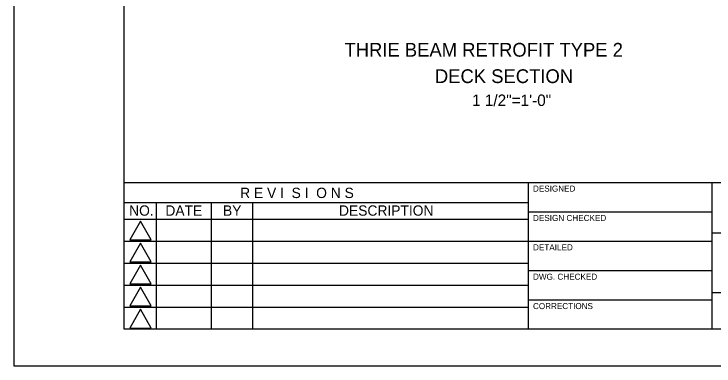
# Model space of a CAD drawing. Extents: x 0 to 22.7, y 0 to 15.7.
# Drawn here: x 0 to 6.35, y 0 to 3.2 of the extents above; entities that cross this region are included whole.
import ezdxf

# ---------------------------------------------------------------- set-up
doc = ezdxf.new("R2010")
doc.units = 0
for name, color, linetype in [('BORDER_ANNO_Cutsheet', 7, 'Continuous'), ('BRDG_ANNO_Anno-Sheet', 7, 'Continuous'), ('BRDG_ANNO_General-Notes', 7, 'Continuous'), ('BRDG_BASE_Active-Point', 7, 'Continuous')]:
    doc.layers.add(name, color=color, linetype=linetype)

msp = doc.modelspace()

# ---------------------------------------------------------------- linework, layer by layer
at = {"layer": 'BORDER_ANNO_Cutsheet'}
msp.add_lwpolyline([(0, 14.6667), (22.6667, 14.6667), (22.6667, 0), (0, 0)], close=True, dxfattribs=at)
at = {"layer": 'BRDG_ANNO_Anno-Sheet'}
for p, q in [((1, 1.6667), (12.8333, 1.6667)), ((4.6667, 0.3333), (4.6667, 1.6667)), ((6.3333, 0.3333), (6.3333, 1.6667)), ((1, 1.4833), (4.6667, 1.4833)), ((1.2917, 0.3333), (1.2917, 1.4833)), ((1.7917, 0.3333), (1.7917, 1.4833)), ((2.1667, 0.3333), (2.1667, 1.4796)), ((4.6667, 1.4), (6.3333, 1.4)), ((0.9983, 1.3333), (4.6667, 1.3333)), ((6.3333, 1.2083), (7.6667, 1.2083)), ((0.9983, 1.1333), (4.6667, 1.1333)), ((4.6667, 1.1333), (6.3333, 1.1333)), ((0.9983, 0.9333), (4.6667, 0.9333)), ((4.6667, 0.8667), (6.3333, 0.8667)), ((0.9983, 0.7333), (4.6667, 0.7333)), ((6.3333, 0.6667), (7.6667, 0.6667)), ((4.6667, 0.6), (6.3333, 0.6)), ((0.9983, 0.5333), (4.6667, 0.5333))]:
    msp.add_line(p, q, dxfattribs=at)
msp.add_lwpolyline([(1, 14.3333), (22.3333, 14.3333), (22.3333, 0.3333), (1, 0.3333)], close=True, dxfattribs=at)
for points in [[(1.1483, 1.3162), (1.0496, 1.145), (1.2429, 1.145), (1.1483, 1.3162)], [(1.1483, 1.1162), (1.0496, 0.945), (1.2429, 0.945), (1.1483, 1.1162)], [(1.1483, 0.9163), (1.0496, 0.745), (1.2429, 0.745), (1.1483, 0.9163)], [(1.1483, 0.7162), (1.0496, 0.545), (1.2429, 0.545), (1.1483, 0.7162)], [(1.1483, 0.5162), (1.0496, 0.345), (1.2429, 0.345), (1.1483, 0.5162)]]:
    msp.add_lwpolyline(points, dxfattribs=at)
at = {"layer": 'BRDG_BASE_Active-Point'}
msp.add_line((0, 0), (0, 0), dxfattribs=at)

# ---------------------------------------------------------------- texts
at = {"layer": 'BRDG_ANNO_Anno-Sheet'}
for s, height, p in [('R E V I  S I  O N S', 0.09375, (2.0516, 1.525)), ('DESIGNED', 0.055, (4.7083, 1.5833)), ('NO.', 0.09375, (1.0444, 1.3646)), ('DATE', 0.09375, (1.3733, 1.3646)), ('BY', 0.09375, (1.8961, 1.3646)), ('DESCRIPTION', 0.09375, (2.9485, 1.3646)), ('DESIGN CHECKED', 0.055207, (4.7083, 1.3167)), ('DETAILED', 0.05521, (4.7083, 1.05)), ('DWG. CHECKED', 0.055207, (4.7083, 0.7833)), ('CORRECTIONS', 0.055, (4.7083, 0.5167))]:
    msp.add_text(s, height=height, dxfattribs=at).set_placement(p)
at = {"layer": 'BRDG_ANNO_General-Notes'}
for s, height, p in [('THRIE BEAM RETROFIT TYPE 2', 0.125, (2.9978, 2.8086)), ('DECK SECTION', 0.125, (3.8182, 2.569)), ('1 1/2"=1\'-0"', 0.104167, (4.1551, 2.3607))]:
    msp.add_text(s, height=height, dxfattribs=at).set_placement(p)

doc.saveas('drawing.dxf')
